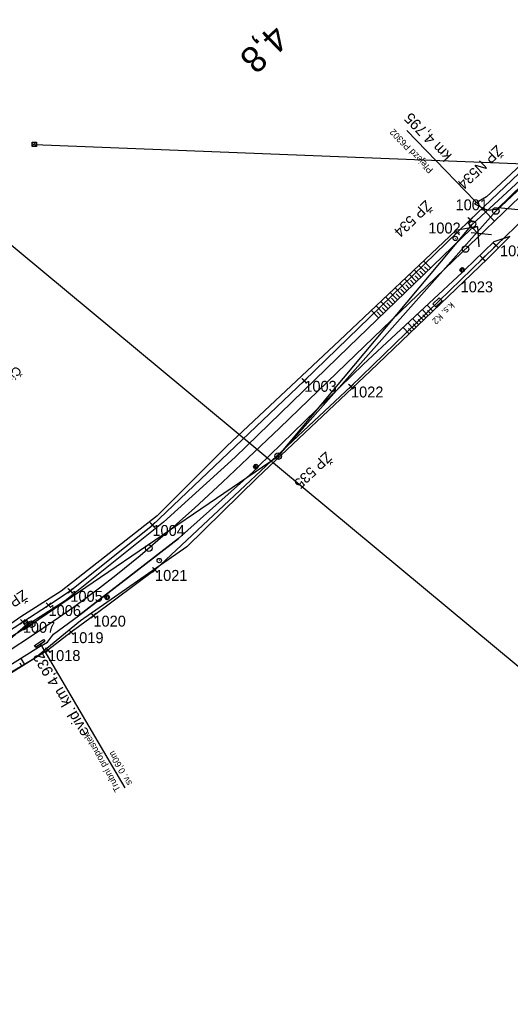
# Model space of a CAD drawing. Extents: x -738085 to -734426, y -1122197 to -1119748.
# Drawn here: x -737800.3 to -737687.7, y -1121962.5 to -1121737.9 of the extents above; entities that cross this region are included whole.
import ezdxf

# ---------------------------------------------------------------- set-up
doc = ezdxf.new("R2010")
doc.units = 0
for name, color, linetype in [('SŽDC', 7, 'Continuous'), ('Vrstva 1', 7, 'Continuous'), ('Vrstva 11', 7, 'Continuous'), ('Vrstva 12', 7, 'Continuous'), ('Vrstva 19', 7, 'Continuous'), ('Vrstva 25', 7, 'Continuous'), ('Vrstva 36', 7, 'Continuous'), ('Vrstva 4', 7, 'Continuous'), ('Vrstva 48', 7, 'Continuous'), ('Vrstva 49', 7, 'Continuous'), ('Vrstva 60', 7, 'Continuous'), ('Vrstva 63', 7, 'Continuous'), ('Vrstva 7', 7, 'Continuous')]:
    doc.layers.add(name, color=color, linetype=linetype)

msp = doc.modelspace()

# ---------------------------------------------------------------- linework, layer by layer
at = {"layer": 'SŽDC'}
for p, q in [((-737696.93, -1121783.83), (-737660.95, -1121749.48)), ((-737684.33, -1121783.29), (-737691.03, -1121789.69)), ((-737691.03, -1121789.69), (-737694.09, -1121792.66)), ((-737694.09, -1121792.66), (-737724.29, -1121822.04)), ((-737799.53, -1121875.99), (-737793.63, -1121872.15)), ((-737783.34, -1121874.58), (-737788.45, -1121878.37))]:
    msp.add_line(p, q, dxfattribs=at)
for points in [[(-737734.99, -1121820.74), (-737699.95, -1121786.71), (-737696.93, -1121783.83)], [(-737793.63, -1121872.15), (-737788.63, -1121868.89), (-737769.81, -1121853.79), (-737734.99, -1121820.74)], [(-737724.29, -1121822.04), (-737769.21, -1121864.09), (-737783.34, -1121874.58)], [(-737883.06, -1121922.16), (-737877.98, -1121919.47), (-737841.63, -1121900.76), (-737807.75, -1121881.35), (-737799.53, -1121875.99)], [(-737788.45, -1121878.37), (-737793.75, -1121882.47), (-737815.25, -1121895.86)]]:
    msp.add_lwpolyline(points, dxfattribs=at)
at = {"layer": 'Vrstva 1'}
msp.add_lwpolyline([(-737451.26, -1121281.58), (-737844.27, -1121754.63), (-737631.21, -1121931.64), (-737238.2, -1121458.59)], close=True, dxfattribs=at)
for points in [[(-737588.06, -1121684.98), (-737606.71, -1121702.84), (-737629.82, -1121725.04), (-737653.84, -1121748.12), (-737672.71, -1121766.23), (-737689.31, -1121782.16)], [(-737588.06, -1121684.98), (-737606.71, -1121702.84), (-737629.82, -1121725.04), (-737653.84, -1121748.12), (-737672.71, -1121766.23), (-737689.31, -1121782.16)], [(-737689.31, -1121782.16), (-737693.43, -1121786.11), (-737700.78, -1121793.17), (-737723.25, -1121814.78), (-737736.16, -1121827.2), (-737740.71, -1121831.57), (-737744.98, -1121835.66), (-737747.9, -1121838.44), (-737753.74, -1121843.99), (-737760.18, -1121849.96), (-737766.24, -1121855.38), (-737772.64, -1121860.85), (-737778.21, -1121865.34), (-737781.95, -1121868.23), (-737787.94, -1121872.67), (-737792.55, -1121875.94), (-737797.07, -1121878.99), (-737803.11, -1121882.92)], [(-737689.31, -1121782.16), (-737693.43, -1121786.11), (-737700.78, -1121793.17), (-737723.25, -1121814.78), (-737736.16, -1121827.2), (-737740.71, -1121831.57), (-737744.98, -1121835.66), (-737747.9, -1121838.44), (-737753.74, -1121843.99), (-737760.18, -1121849.96), (-737766.24, -1121855.38), (-737772.64, -1121860.85), (-737778.21, -1121865.34), (-737781.95, -1121868.23), (-737787.94, -1121872.67), (-737792.55, -1121875.94), (-737797.07, -1121878.99), (-737803.11, -1121882.92)]]:
    msp.add_lwpolyline(points, dxfattribs=at)
at = {"layer": 'Vrstva 11'}
for p, q in [((-737698.94, -1121794.84), (-737698.96, -1121795.76)), ((-737698.56, -1121794.85), (-737698.58, -1121795.77)), ((-737746.27, -1121839.93), (-737746.29, -1121840.85)), ((-737745.89, -1121839.95), (-737745.91, -1121840.86)), ((-737780.31, -1121869.89), (-737780.42, -1121870.8)), ((-737779.94, -1121869.94), (-737780.05, -1121870.85))]:
    msp.add_line(p, q, dxfattribs=at)
for centre in [(-737698.77, -1121795.3), (-737746.1, -1121840.4), (-737780.19, -1121870.37)]:
    msp.add_circle(centre, 0.5, dxfattribs=at)
at = {"layer": 'Vrstva 12'}
for p, q in [((-737698.18, -1121795.31), (-737698.78, -1121795.89)), ((-737745.53, -1121840.41), (-737746.11, -1121840.96))]:
    msp.add_line(p, q, dxfattribs=at)
for points in [[(-737699.35, -1121795.29), (-737698.76, -1121794.72), (-737698.18, -1121795.31), (-737698.78, -1121795.89), (-737699.35, -1121795.29)], [(-737698.76, -1121794.72), (-737698.18, -1121795.31), (-737698.18, -1121795.31)], [(-737699.35, -1121795.29), (-737698.78, -1121795.89), (-737698.78, -1121795.89)], [(-737746.66, -1121840.38), (-737746.08, -1121839.83), (-737745.53, -1121840.41), (-737746.11, -1121840.96), (-737746.66, -1121840.38)], [(-737746.08, -1121839.83), (-737745.53, -1121840.41), (-737745.53, -1121840.41)], [(-737746.66, -1121840.38), (-737746.11, -1121840.96), (-737746.11, -1121840.96)], [(-737780.75, -1121870.28), (-737780.1, -1121869.81), (-737779.63, -1121870.45), (-737780.27, -1121870.93), (-737780.75, -1121870.28)]]:
    msp.add_lwpolyline(points, dxfattribs=at)
at = {"layer": 'Vrstva 19'}
for p, q in [((-737799.5, -1121877.41), (-737799.25, -1121877.82)), ((-737797.45, -1121876.04), (-737797.14, -1121876.44)), ((-737794.78, -1121880.01), (-737794.51, -1121880.44)), ((-737796.84, -1121881.38), (-737796.56, -1121881.79)), ((-737795.48, -1121881.08), (-737776.11, -1121914.07))]:
    msp.add_line(p, q, dxfattribs=at)
for points in [[(-737798.09, -1121876.39), (-737798.63, -1121875.69), (-737799.43, -1121876.25), (-737798.88, -1121876.94)], [(-737799.25, -1121877.82), (-737799.5, -1121877.41), (-737797.45, -1121876.04), (-737797.14, -1121876.44), (-737799.25, -1121877.82)], [(-737797.45, -1121876.04), (-737797.45, -1121876.04), (-737798.09, -1121876.39), (-737798.88, -1121876.94), (-737799.5, -1121877.41), (-737799.5, -1121877.41)], [(-737796.56, -1121881.79), (-737796.84, -1121881.38), (-737794.78, -1121880.01), (-737794.51, -1121880.44), (-737796.56, -1121881.79)], [(-737796.56, -1121881.79), (-737796.84, -1121881.38), (-737794.78, -1121880.01), (-737794.51, -1121880.44), (-737796.56, -1121881.79)], [(-737796.56, -1121881.79), (-737796.56, -1121881.79), (-737794.51, -1121880.44), (-737794.51, -1121880.44)]]:
    msp.add_lwpolyline(points, dxfattribs=at)
at = {"layer": 'Vrstva 25'}
msp.add_line((-737796.88, -1121766.52), (-737537.22, -1121776.8), dxfattribs=at)
at = {"layer": 'Vrstva 36'}
for p, q in [((-737796.48, -1121766.03), (-737797.4, -1121766.88)), ((-737797.04, -1121766.01), (-737797.37, -1121766.32)), ((-737796.38, -1121766.49), (-737796.95, -1121767.02))]:
    msp.add_line(p, q, dxfattribs=at)
for points in [[(-737796.4, -1121767.04), (-737797.4, -1121767), (-737797.36, -1121766), (-737796.36, -1121766.04), (-737796.4, -1121767.04)], [(-737704.06, -1121801.69), (-737703.36, -1121802.41), (-737704.81, -1121803.8), (-737705.5, -1121803.08), (-737704.06, -1121801.69)]]:
    msp.add_lwpolyline(points, dxfattribs=at)
at = {"layer": 'Vrstva 4'}
for p, q in [((-737711.5, -1121763.32), (-737691.38, -1121784.14)), ((-737690.51, -1121781), (-737685.93, -1121781.44)), ((-737689.31, -1121782.16), (-737693.43, -1121786.11)), ((-737697.25, -1121784.1), (-737697.97, -1121784.79)), ((-737697.61, -1121784.44), (-737695.18, -1121786.97)), ((-737695.26, -1121785.45), (-737695, -1121790.05)), ((-737692.11, -1121787.28), (-737696.7, -1121786.83)), ((-737786.78, -1121874.59), (-737763.81, -1121856.91))]:
    msp.add_line(p, q, dxfattribs=at)
at = {"layer": 'Vrstva 48'}
for p, q in [((-737707.16, -1121795.9), (-737708.73, -1121794.27)), ((-737706.08, -1121794.86), (-737707.64, -1121793.24)), ((-737706.62, -1121795.38), (-737707.4, -1121794.57)), ((-737709.32, -1121797.98), (-737710.91, -1121796.33)), ((-737708.24, -1121796.94), (-737709.82, -1121795.3)), ((-737708.78, -1121797.46), (-737709.57, -1121796.64)), ((-737707.7, -1121796.42), (-737708.49, -1121795.6)), ((-737712.55, -1121801.11), (-737714.19, -1121799.42)), ((-737711.47, -1121800.07), (-737713.09, -1121798.39)), ((-737710.4, -1121799.03), (-737712, -1121797.36)), ((-737710.94, -1121799.55), (-737711.74, -1121798.71)), ((-737709.86, -1121798.5), (-737710.66, -1121797.68)), ((-737714.71, -1121803.19), (-737716.37, -1121801.48)), ((-737713.63, -1121802.15), (-737715.28, -1121800.45)), ((-737714.17, -1121802.67), (-737715, -1121801.82)), ((-737713.09, -1121801.63), (-737713.91, -1121800.78)), ((-737712.01, -1121800.59), (-737712.83, -1121799.75)), ((-737716.87, -1121805.28), (-737718.55, -1121803.54)), ((-737715.79, -1121804.24), (-737717.46, -1121802.51)), ((-737716.33, -1121804.76), (-737717.17, -1121803.89)), ((-737715.25, -1121803.72), (-737716.08, -1121802.85)), ((-737705.52, -1121804.77), (-737706.85, -1121803.38)), ((-737717.95, -1121806.32), (-737719.64, -1121804.57)), ((-737717.41, -1121805.8), (-737718.25, -1121804.93)), ((-737707.69, -1121806.84), (-737709.05, -1121805.42)), ((-737706.6, -1121805.8), (-737707.95, -1121804.4)), ((-737707.15, -1121806.32), (-737707.82, -1121805.61)), ((-737706.06, -1121805.28), (-737706.73, -1121804.59)), ((-737710.94, -1121809.95), (-737712.35, -1121808.48)), ((-737709.85, -1121808.92), (-737711.25, -1121807.46)), ((-737708.77, -1121807.88), (-737710.15, -1121806.44)), ((-737709.31, -1121808.4), (-737710.01, -1121807.67)), ((-737708.23, -1121807.36), (-737708.92, -1121806.64)), ((-737710.4, -1121809.43), (-737711.1, -1121808.7)), ((-737799.09, -1121885.75), (-737799.9, -1121884.39)), ((-737799.74, -1121886.13), (-737800.14, -1121885.46))]:
    msp.add_line(p, q, dxfattribs=at)
at = {"layer": 'Vrstva 49'}
msp.add_line((-737763.81, -1121856.91), (-737786.78, -1121874.59), dxfattribs=at)
for points in [[(-737576.15, -1121670.34), (-737594.92, -1121686.44), (-737634.25, -1121723.48), (-737693.22, -1121778.57), (-737695.95, -1121780.13)], [(-737695.95, -1121780.13), (-737693.1, -1121781.63), (-737690.77, -1121781.4), (-737632.01, -1121724.06), (-737595.71, -1121689.55), (-737576.15, -1121670.34)], [(-737695.31, -1121785.35), (-737700.22, -1121786.24), (-737726.94, -1121811.46), (-737752.76, -1121835.69), (-737768.71, -1121851.71), (-737790.7, -1121868.99), (-737799.98, -1121874.85), (-737805.62, -1121878.7), (-737815.69, -1121888.11)], [(-737695.31, -1121785.35), (-737696.84, -1121785.93), (-737724.76, -1121812.91), (-737750.86, -1121838.21), (-737767.3, -1121853.16), (-737789.85, -1121871.2)], [(-737687.85, -1121787.68), (-737693.02, -1121792.8), (-737719.88, -1121818.52), (-737745.76, -1121842.95), (-737761.93, -1121858.78), (-737786.27, -1121875.73)], [(-737687.85, -1121787.68), (-737691.53, -1121788.83), (-737698.18, -1121795.31), (-737698.78, -1121795.89), (-737721.51, -1121816.97), (-737745.53, -1121840.41), (-737746.11, -1121840.96), (-737746.8, -1121841.68), (-737763.81, -1121856.91)], [(-737789.85, -1121871.2), (-737797.45, -1121876.04), (-737798.09, -1121876.39), (-737798.63, -1121875.69), (-737799.43, -1121876.25), (-737798.88, -1121876.94), (-737799.5, -1121877.41), (-737802.33, -1121879.9), (-737815.69, -1121888.11)], [(-737786.27, -1121875.73), (-737796.58, -1121884.26), (-737812.31, -1121893.58), (-737836.37, -1121907.15), (-737853.54, -1121916.34), (-737876.33, -1121929.15)], [(-737795.35, -1121881.51), (-737793.86, -1121880.65), (-737792.48, -1121878.83), (-737786.78, -1121874.59)], [(-737795.35, -1121881.51), (-737796.51, -1121882.29), (-737812.07, -1121891.92), (-737813.49, -1121892.88), (-737814.19, -1121893.27), (-737836.65, -1121905.4), (-737854.29, -1121914.96), (-737871.1, -1121924.02), (-737871.81, -1121924.39), (-737878.69, -1121927.9), (-737890.84, -1121935.62)]]:
    msp.add_lwpolyline(points, dxfattribs=at)
at = {"layer": 'Vrstva 60'}
for p, q in [((-737696.48, -1121784.28), (-737697.48, -1121783.28)), ((-737696.48, -1121783.38), (-737697.48, -1121784.38)), ((-737697.38, -1121784.28), (-737696.38, -1121783.28)), ((-737697.38, -1121783.38), (-737696.38, -1121784.38)), ((-737696.93, -1121783.83), (-737696.93, -1121783.83)), ((-737699.5, -1121787.16), (-737700.5, -1121786.16)), ((-737699.5, -1121786.26), (-737700.5, -1121787.26)), ((-737700.4, -1121787.16), (-737699.4, -1121786.16)), ((-737700.4, -1121786.26), (-737699.4, -1121787.26)), ((-737699.95, -1121786.71), (-737699.95, -1121786.71)), ((-737690.58, -1121790.14), (-737691.58, -1121789.14)), ((-737690.58, -1121789.24), (-737691.58, -1121790.24)), ((-737691.48, -1121790.14), (-737690.48, -1121789.14)), ((-737691.48, -1121789.24), (-737690.48, -1121790.24)), ((-737691.03, -1121789.69), (-737691.03, -1121789.69)), ((-737693.64, -1121793.11), (-737694.64, -1121792.11)), ((-737693.64, -1121792.21), (-737694.64, -1121793.21)), ((-737694.54, -1121793.11), (-737693.54, -1121792.11)), ((-737694.54, -1121792.21), (-737693.54, -1121793.21)), ((-737694.09, -1121792.66), (-737694.09, -1121792.66)), ((-737734.54, -1121821.19), (-737735.54, -1121820.19)), ((-737734.54, -1121820.29), (-737735.54, -1121821.29)), ((-737735.44, -1121821.19), (-737734.44, -1121820.19)), ((-737735.44, -1121820.29), (-737734.44, -1121821.29)), ((-737734.99, -1121820.74), (-737734.99, -1121820.74)), ((-737723.84, -1121822.49), (-737724.84, -1121821.49)), ((-737723.84, -1121821.59), (-737724.84, -1121822.59)), ((-737724.74, -1121822.49), (-737723.74, -1121821.49)), ((-737724.74, -1121821.59), (-737723.74, -1121822.59)), ((-737724.29, -1121822.04), (-737724.29, -1121822.04)), ((-737769.36, -1121854.24), (-737770.36, -1121853.24)), ((-737769.36, -1121853.34), (-737770.36, -1121854.34)), ((-737770.26, -1121854.24), (-737769.26, -1121853.24)), ((-737770.26, -1121853.34), (-737769.26, -1121854.34)), ((-737769.81, -1121853.79), (-737769.81, -1121853.79)), ((-737768.76, -1121864.54), (-737769.76, -1121863.54)), ((-737768.76, -1121863.64), (-737769.76, -1121864.64)), ((-737769.66, -1121864.54), (-737768.66, -1121863.54)), ((-737769.66, -1121863.64), (-737768.66, -1121864.64)), ((-737769.21, -1121864.09), (-737769.21, -1121864.09)), ((-737788.18, -1121869.34), (-737789.18, -1121868.34)), ((-737788.18, -1121868.44), (-737789.18, -1121869.44)), ((-737789.08, -1121869.34), (-737788.08, -1121868.34)), ((-737789.08, -1121868.44), (-737788.08, -1121869.44)), ((-737788.63, -1121868.89), (-737788.63, -1121868.89)), ((-737793.18, -1121872.6), (-737794.18, -1121871.6)), ((-737793.18, -1121871.7), (-737794.18, -1121872.7)), ((-737794.08, -1121872.6), (-737793.08, -1121871.6)), ((-737794.08, -1121871.7), (-737793.08, -1121872.7)), ((-737793.63, -1121872.15), (-737793.63, -1121872.15)), ((-737799.08, -1121876.44), (-737800.08, -1121875.44)), ((-737799.08, -1121875.54), (-737800.08, -1121876.54)), ((-737799.98, -1121876.44), (-737798.98, -1121875.44)), ((-737799.98, -1121875.54), (-737798.98, -1121876.54)), ((-737782.89, -1121875.03), (-737783.89, -1121874.03)), ((-737782.89, -1121874.13), (-737783.89, -1121875.13)), ((-737783.79, -1121875.03), (-737782.79, -1121874.03)), ((-737783.79, -1121874.13), (-737782.79, -1121875.13)), ((-737783.34, -1121874.58), (-737783.34, -1121874.58)), ((-737799.53, -1121875.99), (-737799.53, -1121875.99)), ((-737788, -1121878.82), (-737789, -1121877.82)), ((-737788, -1121877.92), (-737789, -1121878.92)), ((-737788.9, -1121878.82), (-737787.9, -1121877.82)), ((-737788.9, -1121877.92), (-737787.9, -1121878.92)), ((-737788.45, -1121878.37), (-737788.45, -1121878.37)), ((-737793.3, -1121882.92), (-737794.3, -1121881.92)), ((-737793.3, -1121882.02), (-737794.3, -1121883.02)), ((-737794.2, -1121882.92), (-737793.2, -1121881.92)), ((-737794.2, -1121882.02), (-737793.2, -1121883.02)), ((-737793.75, -1121882.47), (-737793.75, -1121882.47))]:
    msp.add_line(p, q, dxfattribs=at)
at = {"layer": 'Vrstva 63'}
for p, q in [((-737696.42, -1121784.79), (-737530.36, -1121631.2)), ((-737691.07, -1121781.8), (-737530.36, -1121631.2)), ((-737691.07, -1121781.8), (-737740.97, -1121838.03)), ((-737691.04, -1121781.76), (-737691.11, -1121781.83)), ((-737740.97, -1121838.03), (-737696.42, -1121784.79)), ((-737696.38, -1121784.76), (-737696.45, -1121784.83)), ((-737797.5, -1121876.53), (-737740.97, -1121838.03)), ((-737740.94, -1121838), (-737741.01, -1121838.07)), ((-737939.91, -1121962.55), (-737797.5, -1121876.53)), ((-737797.46, -1121876.5), (-737797.54, -1121876.56))]:
    msp.add_line(p, q, dxfattribs=at)
for centre in [(-737691.07, -1121781.8), (-737696.42, -1121784.79), (-737740.97, -1121838.03), (-737797.5, -1121876.53)]:
    msp.add_circle(centre, 0.756, dxfattribs=at)
at = {"layer": 'Vrstva 7'}
for p, q in [((-737700.34, -1121788.04), (-737700.41, -1121788.11)), ((-737768.19, -1121861.9), (-737768.27, -1121861.96))]:
    msp.add_line(p, q, dxfattribs=at)
for centre, radius in [((-737700.38, -1121788.07), 0.5), ((-737698.02, -1121790.52), 0.75), ((-737698.02, -1121790.52), 0.75), ((-737770.62, -1121859.12), 0.75), ((-737770.62, -1121859.12), 0.75), ((-737768.23, -1121861.93), 0.5)]:
    msp.add_circle(centre, radius, dxfattribs=at)

# ---------------------------------------------------------------- texts
at = {"layer": 'Vrstva 1'}
msp.add_text('Číslo ověření:', height=2, rotation=230.2802, dxfattribs=at).set_placement((-737801.15, -1121817.19))
at = {"layer": 'Vrstva 19'}
for s, height, rotation, p in [('evid. km 4,932', 2.5, 120.4054, (-737784.21, -1121901.42)), ('Trubní propustek', 1.5, 119.1298, (-737777.04, -1121914.46)), ('sv. 0,60m', 1.5, 119.1298, (-737774.42, -1121913))]:
    msp.add_text(s, height=height, rotation=rotation, dxfattribs=at).set_placement(p)
at = {"layer": 'Vrstva 36'}
msp.add_text('k.s. K2', height=1.5, rotation=223.881, dxfattribs=at).set_placement((-737701.41, -1121802.62))
at = {"layer": 'Vrstva 4'}
for s, height, rotation, p in [('km 4,795', 2.5, 133.8161, (-737700.99, -1121768.96)), ('Přejezd P6302', 1.5, 134.0191, (-737705.34, -1121772.29))]:
    msp.add_text(s, height=height, rotation=rotation, dxfattribs=at).set_placement(p)
at = {"layer": 'Vrstva 60'}
for s, p in [('1001', (-737700.32, -1121781.64)), ('1002', (-737706.58, -1121786.95)), ('1024', (-737690.12, -1121792.19)), ('1023', (-737699.16, -1121800.44)), ('1003', (-737734.99, -1121823.24)), ('1022', (-737724.29, -1121824.54)), ('1004', (-737769.81, -1121856.29)), ('1021', (-737769.21, -1121866.59)), ('1005', (-737788.63, -1121871.39)), ('1006', (-737793.63, -1121874.65)), ('1007', (-737799.53, -1121878.49)), ('1020', (-737783.34, -1121877.08)), ('1019', (-737788.45, -1121880.87)), ('1018', (-737793.75, -1121884.97))]:
    msp.add_text(s, height=2.5, dxfattribs=at).set_placement(p)
at = {"layer": 'Vrstva 63'}
for s, rotation, p in [('ŽP N534', 223.8625, (-737690.94, -1121766.54)), ('ŽP 534', 223.8625, (-737707.19, -1121779.16)), ('ŽP 535', 223.543, (-737730.06, -1121836.82)), ('ŽP 536', 214.0718, (-737799.52, -1121868.52))]:
    msp.add_text(s, height=2.4, rotation=rotation, dxfattribs=at).set_placement(p)
at = {"layer": 'Vrstva 7'}
msp.add_text('4,8', height=6, rotation=223.8625, dxfattribs=at).set_placement((-737742.19, -1121738.67))
msp.add_text('4,8', height=6, rotation=223.8625, dxfattribs=at).set_placement((-737742.19, -1121738.67))

doc.saveas('drawing.dxf')
